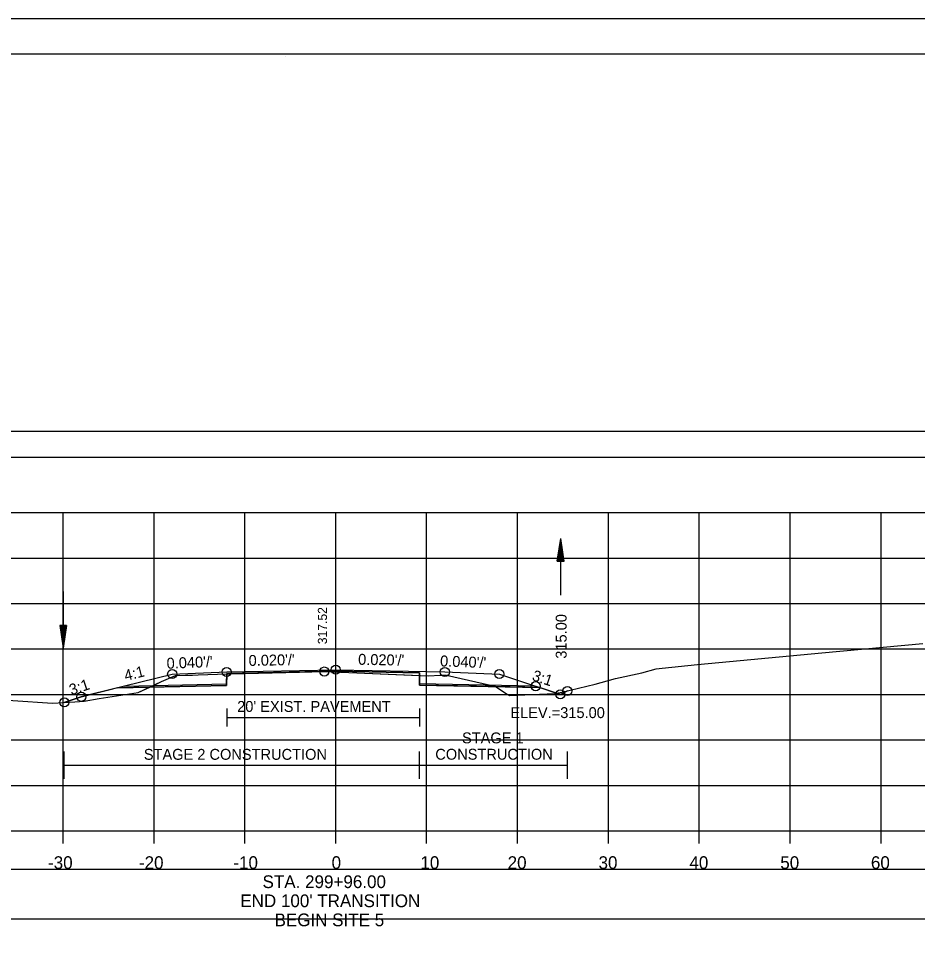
# Model space of a CAD drawing. Extents: x 1376273 to 1384221, y 378927 to 384592.
# Drawn here: x 1381323.4 to 1381422.4, y 379796.7 to 379898.5 of the extents above; entities that cross this region are included whole.
import ezdxf

# ---------------------------------------------------------------- set-up
doc = ezdxf.new("R2010")
doc.units = 0
for name, color, linetype in [('R_Alt Surface', 7, 'Continuous'), ('R_Axis', 7, 'Continuous'), ('R_Axis Annot', 7, 'Continuous'), ('R_Border', 7, 'Continuous'), ('R_Border Notes', 7, 'Continuous'), ('R_Contours', 7, 'Continuous'), ('R_Dimension', 7, 'Continuous'), ('R_Exist Surface', 7, 'Continuous'), ('R_Fin Surface', 7, 'Continuous'), ('R_Grid', 7, 'Continuous'), ('R_No Plot', 7, 'Continuous'), ('R_Water', 7, 'Continuous'), ('R_Xsect Elev', 7, 'Continuous'), ('R_Xsect Slope', 7, 'Continuous'), ('T_Detection Zones', 7, 'Continuous')]:
    doc.layers.add(name, color=color, linetype=linetype)

msp = doc.modelspace()

# ---------------------------------------------------------------- linework, layer by layer
at = {"layer": 'R_Alt Surface'}
for points in [[(1381335.07, 379825.06), (1381346.34, 379825.29), (1381346.35, 379826.45), (1381358.35, 379826.69), (1381367.56, 379826.51), (1381367.57, 379825.34), (1381380.22, 379825.09)], [(1381346.35, 379822.61), (1381346.35, 379820.61)], [(1381367.56, 379822.61), (1381367.56, 379820.61)], [(1381346.35, 379821.61), (1381367.56, 379821.61)]]:
    msp.add_lwpolyline(points, dxfattribs=at)
at = {"layer": 'R_Axis'}
for p, q in [((1381208.35, 379809.14), (1381508.35, 379809.14)), ((1381328.35, 379807.74), (1381328.35, 379809.14)), ((1381338.35, 379807.74), (1381338.35, 379809.14)), ((1381348.35, 379807.74), (1381348.35, 379809.14)), ((1381358.35, 379807.74), (1381358.35, 379809.14)), ((1381368.35, 379807.74), (1381368.35, 379809.14)), ((1381378.35, 379807.74), (1381378.35, 379809.14)), ((1381388.35, 379807.74), (1381388.35, 379809.14)), ((1381398.35, 379807.74), (1381398.35, 379809.14)), ((1381408.35, 379807.74), (1381408.35, 379809.14)), ((1381418.35, 379807.74), (1381418.35, 379809.14))]:
    msp.add_line(p, q, dxfattribs=at)
at = {"layer": 'R_Axis Annot'}
for points in [[(1381207.46, 379850.23), (1381509.26, 379850.23), (1381509.26, 379853.05), (1381207.46, 379853.05)], [(1381207.5, 379799.46), (1381509.19, 379799.46), (1381509.19, 379804.87), (1381207.5, 379804.87)]]:
    msp.add_lwpolyline(points, close=True, dxfattribs=at)
at = {"layer": 'R_Border'}
for p, q in [((1381200.35, 379894.6), (1381516.53, 379894.6)), ((1381352.87, 379894.34), (1381352.87, 379894.34)), ((1381352.87, 379894.34), (1381352.87, 379894.34))]:
    msp.add_line(p, q, dxfattribs=at)
at = {"layer": 'R_Contours'}
for points in [[(1381367.56, 379826.23), (1381368.56, 379826.18), (1381369.85, 379826.25), (1381370.54, 379826.26), (1381375.36, 379825.16), (1381375.77, 379825.11), (1381375.92, 379825.01), (1381367.57, 379825.17)], [(1381375.92, 379825.01), (1381377.26, 379824.14), (1381377.45, 379824.03), (1381377.51, 379824.04), (1381382.42, 379824.25), (1381382.63, 379824.28), (1381380.75, 379824.91)], [(1381382.63, 379824.28), (1381383.22, 379824.39), (1381383.84, 379824.53), (1381383.06, 379824.14)]]:
    msp.add_lwpolyline(points, close=True, dxfattribs=at)
at = {"layer": 'R_Dimension'}
for p, q in [((1381328.48, 379814.85), (1381328.48, 379817.85)), ((1381367.56, 379814.85), (1381367.56, 379817.85)), ((1381383.84, 379814.85), (1381383.84, 379817.85)), ((1381328.48, 379816.35), (1381383.84, 379816.35))]:
    msp.add_line(p, q, dxfattribs=at)
at = {"layer": 'R_Exist Surface'}
msp.add_lwpolyline([(1381318.42, 379823.76), (1381327.19, 379823.18), (1381329.62, 379823.32), (1381330.65, 379823.4), (1381332.32, 379823.68), (1381336.62, 379824.36), (1381339.18, 379825.55), (1381340.72, 379826.22), (1381341.81, 379826.25), (1381342.59, 379826.27), (1381343.2, 379826.29), (1381345.35, 379826.37), (1381354.37, 379826.59), (1381357.08, 379826.66), (1381359.78, 379826.56), (1381368.56, 379826.18), (1381369.85, 379826.25), (1381370.54, 379826.26), (1381375.36, 379825.16), (1381375.77, 379825.11), (1381377.26, 379824.14), (1381377.45, 379824.03), (1381377.51, 379824.04), (1381382.42, 379824.25), (1381383.22, 379824.39), (1381386.9, 379825.26), (1381389.11, 379825.9), (1381392.03, 379826.51), (1381393.59, 379826.97), (1381394.28, 379827.03), (1381398.15, 379827.44), (1381411.84, 379828.71), (1381422.94, 379829.74)], dxfattribs=at)
at = {"layer": 'R_Fin Surface'}
msp.add_lwpolyline([(1381328.48, 379823.26), (1381330.35, 379823.88), (1381335.1, 379825.07), (1381340.35, 379826.38), (1381346.35, 379826.62), (1381358.35, 379826.86), (1381370.35, 379826.62), (1381376.35, 379826.38), (1381380.2, 379825.09), (1381380.35, 379825.05), (1381383.06, 379824.14), (1381383.84, 379824.53)], dxfattribs=at)
at = {"layer": 'R_Grid'}
for p, q in [((1381208.35, 379844.14), (1381508.35, 379844.14)), ((1381328.35, 379809.14), (1381328.35, 379844.14)), ((1381338.35, 379809.14), (1381338.35, 379844.14)), ((1381348.35, 379809.14), (1381348.35, 379844.14)), ((1381358.35, 379809.14), (1381358.35, 379844.14)), ((1381368.35, 379809.14), (1381368.35, 379844.14)), ((1381378.35, 379809.14), (1381378.35, 379844.14)), ((1381388.35, 379809.14), (1381388.35, 379844.14)), ((1381398.35, 379809.14), (1381398.35, 379844.14)), ((1381408.35, 379809.14), (1381408.35, 379844.14)), ((1381418.35, 379809.14), (1381418.35, 379844.14)), ((1381208.35, 379839.14), (1381508.35, 379839.14)), ((1381208.35, 379834.14), (1381508.35, 379834.14)), ((1381208.35, 379829.14), (1381508.35, 379829.14)), ((1381208.35, 379824.14), (1381508.35, 379824.14)), ((1381208.35, 379819.14), (1381508.35, 379819.14)), ((1381208.35, 379814.14), (1381508.35, 379814.14)), ((1381208.35, 379809.14), (1381508.35, 379809.14))]:
    msp.add_line(p, q, dxfattribs=at)
at = {"layer": 'R_No Plot'}
msp.add_line((1381187.95, 379898.5), (1381521.28, 379898.5), dxfattribs=at)
for points in [[(1381187.94, 379898.5), (1381521.28, 379898.5), (1381521.28, 379685.16), (1381187.94, 379685.16)], [(1381434.27, 379894.6), (1381434.27, 379884.72), (1381470, 379884.72), (1381470, 379881.8), (1381493.2, 379881.8), (1381493.2, 379857.47), (1381516.53, 379857.47), (1381516.53, 379689.14), (1381200.35, 379689.14), (1381200.35, 379894.6)]]:
    msp.add_lwpolyline(points, close=True, dxfattribs=at)
msp.add_lwpolyline([(1381334.35, 379824.88), (1381346.34, 379825.12), (1381346.35, 379826.45), (1381358.35, 379826.69), (1381367.56, 379826.51), (1381367.57, 379825.17), (1381380.75, 379824.91)], dxfattribs=at)
for centre in [(1381340.35, 379826.38), (1381346.35, 379826.62), (1381357.08, 379826.66), (1381358.35, 379826.86), (1381370.35, 379826.62), (1381376.35, 379826.38), (1381380.35, 379825.05), (1381383.06, 379824.14), (1381383.06, 379824.14), (1381383.84, 379824.53), (1381328.48, 379823.26), (1381330.35, 379823.88)]:
    msp.add_circle(centre, 0.5, dxfattribs=at)
at = {"layer": 'R_Water'}
for p, q in [((1381382.72, 379838.8), (1381383.1, 379841.3)), ((1381382.78, 379838.8), (1381383.1, 379840.88)), ((1381383.1, 379835.05), (1381383.1, 379841.3)), ((1381383.47, 379838.8), (1381383.1, 379841.3)), ((1381383.41, 379838.8), (1381383.1, 379840.88)), ((1381382.85, 379838.8), (1381383.1, 379840.45)), ((1381382.91, 379838.8), (1381383.1, 379840.03)), ((1381383.34, 379838.8), (1381383.1, 379840.45)), ((1381383.28, 379838.8), (1381383.1, 379840.03)), ((1381382.72, 379838.8), (1381383.47, 379838.8)), ((1381382.97, 379838.8), (1381383.1, 379839.61)), ((1381383.04, 379838.8), (1381383.1, 379839.19)), ((1381383.22, 379838.8), (1381383.1, 379839.61)), ((1381383.15, 379838.8), (1381383.1, 379839.19)), ((1381328.35, 379835.47), (1381328.35, 379829.22)), ((1381327.97, 379831.72), (1381328.35, 379829.22)), ((1381328.72, 379831.72), (1381327.97, 379831.72)), ((1381328.03, 379831.72), (1381328.35, 379829.63)), ((1381328.1, 379831.72), (1381328.35, 379830.06)), ((1381328.16, 379831.72), (1381328.35, 379830.48)), ((1381328.22, 379831.72), (1381328.35, 379830.9)), ((1381328.29, 379831.72), (1381328.35, 379831.32)), ((1381328.72, 379831.72), (1381328.35, 379829.22)), ((1381328.47, 379831.72), (1381328.35, 379830.9)), ((1381328.6, 379831.72), (1381328.35, 379830.06)), ((1381328.66, 379831.72), (1381328.35, 379829.63)), ((1381328.53, 379831.72), (1381328.35, 379830.48)), ((1381328.41, 379831.72), (1381328.35, 379831.32))]:
    msp.add_line(p, q, dxfattribs=at)
at = {"layer": 'T_Detection Zones'}
for points in [[(1381346.35, 379826.39), (1381354.37, 379826.59), (1381357.08, 379826.66), (1381359.78, 379826.56), (1381367.56, 379826.23), (1381367.56, 379826.51), (1381358.35, 379826.69), (1381346.35, 379826.45)], [(1381337.89, 379824.95), (1381339.18, 379825.55), (1381340.72, 379826.22), (1381341.81, 379826.25), (1381342.59, 379826.27), (1381343.2, 379826.29), (1381345.35, 379826.37), (1381346.35, 379826.39), (1381346.34, 379825.12)], [(1381328.48, 379823.26), (1381329.62, 379823.32), (1381330.65, 379823.4), (1381332.32, 379823.68), (1381336.62, 379824.36), (1381337.89, 379824.95), (1381334.35, 379824.88), (1381330.35, 379823.88)]]:
    msp.add_lwpolyline(points, close=True, dxfattribs=at)

# ---------------------------------------------------------------- texts
at = {"layer": 'R_Alt Surface'}
msp.add_text("20' EXIST. PAVEMENT", height=1.2, dxfattribs=at).set_placement((1381347.5, 379822.22))
at = {"layer": 'R_Axis Annot'}
for s, p in [('-30', (1381326.69, 379804.94)), ('-20', (1381336.69, 379804.94)), ('-10', (1381347.08, 379804.94)), ('0', (1381357.89, 379804.94)), ('10', (1381367.66, 379804.94)), ('20', (1381377.26, 379804.94)), ('30', (1381387.26, 379804.94)), ('40', (1381397.26, 379804.94)), ('50', (1381407.26, 379804.94)), ('60', (1381417.23, 379804.94)), ('STA. 299+96.00', (1381350.29, 379802.84)), ("END 100' TRANSITION", (1381347.84, 379800.74)), ('BEGIN SITE 5', (1381351.61, 379798.64))]:
    msp.add_text(s, height=1.4, dxfattribs=at).set_placement(p)
at = {"layer": 'R_Border Notes'}
msp.add_text('ELEV.=315.00', height=1.2, dxfattribs=at).set_placement((1381377.56, 379821.54))
at = {"layer": 'R_Dimension'}
for s, p in [('STAGE 1 ', (1381372.24, 379818.76)), ('STAGE 2 CONSTRUCTION', (1381337.23, 379816.95)), ('CONSTRUCTION', (1381369.3, 379816.96))]:
    msp.add_text(s, height=1.2, dxfattribs=at).set_placement(p)
at = {"layer": 'R_Xsect Elev'}
for s, height, p in [('317.52', 1, (1381357.38, 379829.66)), ('315.00', 1.2, (1381383.75, 379828.07))]:
    msp.add_text(s, height=height, rotation=90, dxfattribs=at).set_placement(p)
at = {"layer": 'R_Xsect Slope'}
for s, rotation, p in [("0.020'/'", 1.1458, (1381348.77, 379827.27)), ("0.020'/'", 358.8542, (1381360.8, 379827.41)), ("0.040'/'", 2.2906, (1381339.76, 379826.96)), ("0.040'/'", 357.7094, (1381369.81, 379827.24)), ('4:1', 14.0362, (1381335.23, 379825.61)), ('3:1', 341.5651, (1381379.86, 379825.73)), ('3:1', 18.4349, (1381329.25, 379824.04))]:
    msp.add_text(s, height=1.2, rotation=rotation, dxfattribs=at).set_placement(p)

doc.saveas('drawing.dxf')
